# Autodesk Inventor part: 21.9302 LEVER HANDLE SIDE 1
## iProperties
Created: 2011-01
Part Number: 21.9302 LEVER HANDLE SIDE 1
Document SubType Name: Modeling
Designer: Administrator
Density: 7.85 g/cm^3
Material: Steel
Mass: 236.592 g
Surface Area: 88.9382 cm^2
Volume: 30.1391 cm^3
Author: Administrator
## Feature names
1. Extrusion1
2. Extrusion2
3. Extrusion3
4. Extrusion4
5. Fillet1
6. Extrusion6
7. Extrusion7
8. Fillet5
